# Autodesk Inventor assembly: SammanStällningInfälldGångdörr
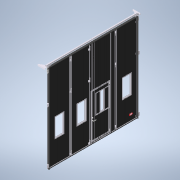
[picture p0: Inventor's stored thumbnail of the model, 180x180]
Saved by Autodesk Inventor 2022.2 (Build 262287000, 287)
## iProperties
Created: 2022-02
Part Number: SammanStällningInfälldGångdörr
Document SubType Name: Assembly
Designer: cl
Author: cl
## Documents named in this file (20)
- G:\AutoCad\Carl Lund\3D-modeller systemlösningar\3D-modell-systemlösning-2022\SammanStällningInfälldGångdörr.iam
- G:\AutoCad\Carl Lund\3D-modeller systemlösningar\3D-modell-systemlösning-2022\Parts\BladKomplett2022.iam
- G:\AutoCad\Carl Lund\3D-modeller systemlösningar\3D-modell-systemlösning-2022\Parts\MellanGångjärnH.ipt
- G:\AutoCad\Carl Lund\3D-modeller systemlösningar\3D-modell-systemlösning-2022\Parts\MellanGångjärnV.ipt
- G:\AutoCad\Carl Lund\3D-modeller systemlösningar\3D-modell-systemlösning-2022\Parts\Karmstyrning.ipt
- G:\AutoCad\Carl Lund\3D-modeller systemlösningar\3D-modell-systemlösning-2022\Parts\KarmgångjärnH.ipt
- G:\AutoCad\Carl Lund\3D-modeller systemlösningar\3D-modell-systemlösning-2022\Parts\KarmgångjärnV.ipt
- G:\AutoCad\Carl Lund\3D-modeller systemlösningar\3D-modell-systemlösning-2022\Parts\SidotätningUppe.ipt
- G:\AutoCad\Carl Lund\3D-modeller systemlösningar\3D-modell-systemlösning-2022\Parts\SidoTätning.ipt
- G:\AutoCad\Carl Lund\3D-modeller systemlösningar\3D-modell-systemlösning-2022\Parts\SläpList.ipt
- G:\AutoCad\Carl Lund\3D-modeller systemlösningar\3D-modell-systemlösning-2022\Parts\GummilistMellan.ipt
- G:\AutoCad\Carl Lund\3D-modeller systemlösningar\3D-modell-systemlösning-2022\Styrande.iam
- G:\AutoCad\Carl Lund\3D-modeller systemlösningar\3D-modell-systemlösning-2022\Parts\GarageregelHöger.ipt
- G:\AutoCad\Carl Lund\3D-modeller systemlösningar\3D-modell-systemlösning-2022\Parts\GarageregelVänster.ipt
- G:\AutoCad\Carl Lund\3D-modeller systemlösningar\3D-modell-systemlösning-2022\Parts\UppställningsbeslagHöger.ipt
- G:\AutoCad\Carl Lund\3D-modeller systemlösningar\3D-modell-systemlösning-2022\Parts\UppställningsbeslagVänster.ipt
- G:\AutoCad\Carl Lund\3D-modeller systemlösningar\3D-modell-systemlösning-2022\Parts\styrrulle.ipt
- G:\AutoCad\Carl Lund\3D-modeller systemlösningar\3D-modell-systemlösning-2022\Parts\Styrskena.ipt
- G:\AutoCad\Carl Lund\3D-modeller systemlösningar\3D-modell-systemlösning-2022\Parts\BladKomplettInfälld2022.iam
- G:\AutoCad\Carl Lund\3D-modeller systemlösningar\3D-modell-systemlösning-2022\Parts\Logga.ipt
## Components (50 placed, 18 different names)
1. BladKomplett2022:1 [sub-assembly] — Mate:1, Mate:2, Flush:1, Flush:2, Flush:3, Flush:8, Flush:28, Flush:29, Mate:28, Flush:30, Mate:42, Flush:73, Mate:39, Mate:43, Mate:47, Mate:48, Flush:99, Flush:100, Flush:101, Flush:102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
2. BladKomplett2022:2 [sub-assembly] — Flush:2, Flush:3, Flush:8, Flush:106, Mate:52, Flush:107, Flush:118, Flush:121, Mate:65, Flush:148, Flush:149, Mate:82, Flush:170, Flush:171, Flush:177
3. BladKomplett2022:3 [sub-assembly] — Flush:30, Flush:101, Flush:102, Mate:53, Flush:114, Flush:115
4. BladKomplett2022:4 [sub-assembly] — Flush:32, Flush:100, Flush:103, Mate:54, Flush:122, Flush:123, Flush:128, Mate:64, Flush:146, Flush:147
5. BladKomplett2022:5 [sub-assembly] — Flush:31, Flush:99, Flush:104, Flush:129, Mate:55, Flush:130, Mate:63, Flush:144, Flush:145, Mate:81, Flush:168, Flush:169
6. Logga:1 — Mate:181, Mate:182, Mate:183
7. BladKomplett2022:6 [sub-assembly] — Mate:28, Flush:28, Flush:29, Flush:31, Flush:32, Mate:38, Flush:74, Mate:49, Mate:50, Flush:131, Flush:134, Flush:137, Mate:56, Flush:138, Flush:139, Mate:58, Mate:59, Mate:62, Flush:142, Flush:143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
8. BladKomplettInfälld2022:1 [sub-assembly] — Flush:176, Flush:177, Flush:178, Mate:177, Flush:179, Flush:180, Flush:181, Mate:178, Flush:187, Flush:188, Flush:189, Mate:180, Flush:190
9. GarageregelHöger:1 — Flush:156, Flush:157, Flush:158
10. GarageregelHöger:2 — Mate:77, Flush:154, Flush:155, Flush:156, Flush:157, Flush:158
11. GarageregelVänster:1 — Flush:161, Flush:162, Flush:163
12. GarageregelVänster:2 — Mate:78, Flush:159, Flush:160, Flush:161, Flush:162, Flush:163
13. Karmstyrning:2 — Mate:38, Mate:56, Flush:138, Flush:141
14. Karmstyrning:3 — Mate:39, Mate:43, Flush:140
15. Karmstyrning:4 — Mate:42, Mate:60, Mate:61, Flush:141
16. KarmgångjärnH:1 — Flush:74, Mate:49, Mate:50, Flush:166, Flush:167, Mate:80
17. KarmgångjärnV:1 — Flush:73, Mate:47, Mate:48, Flush:164, Flush:165, Mate:79
18. Karmstyrning:1 — Flush:139, Mate:58, Mate:59, Flush:140
19. MellanGångjärnV:3 — Flush:110, Flush:111, Flush:113
20. MellanGångjärnV:2 — Flush:108, Flush:109, Flush:110, Flush:111, Flush:112
21. MellanGångjärnV:1 — Flush:106, Mate:52, Flush:107, Flush:108, Flush:109
22. MellanGångjärnH:2 — Flush:116, Flush:117, Flush:118, Flush:119, Flush:120
23. MellanGångjärnH:3 — Flush:119, Flush:120, Flush:121
24. MellanGångjärnH:1 — Mate:53, Flush:114, Flush:115, Flush:116, Flush:117
25. MellanGångjärnV:6 — Flush:124, Flush:125, Flush:126, Flush:127, Flush:128
26. MellanGångjärnV:5 — Flush:126, Flush:127, Flush:129
27. MellanGångjärnV:4 — Mate:54, Flush:122, Flush:123, Flush:124, Flush:125
28. MellanGångjärnH:5 — Flush:132, Flush:133, Flush:134
29. MellanGångjärnH:6 — Flush:135, Flush:136, Flush:137
30. MellanGångjärnH:4 — Mate:55, Flush:130, Flush:131, Flush:132, Flush:133, Flush:135, Flush:136
31. MellanGångjärnV:7 — Flush:181, Mate:178, Flush:182, Flush:183, Flush:184, Flush:185, Flush:186
32. MellanGångjärnV:8 — Flush:183, Flush:184, Flush:187
33. MellanGångjärnV:9 — Flush:185, Flush:186, Flush:188
34. GummilistMellan:6 — Mate:177, Flush:179, Flush:180
35. GummilistMellan:2 — Mate:63, Flush:144, Flush:145
36. GummilistMellan:3 — Mate:64, Flush:146, Flush:147
37. GummilistMellan:4 — Mate:65, Flush:148, Flush:149
38. GummilistMellan:5 — Mate:66, Flush:150, Flush:151
39. SidotätningUppe:1 — Mate:67, Mate:68, Flush:152, Mate:71, Mate:74
40. SidoTätning:1 — Mate:69, Mate:70, Mate:71, Mate:76
41. SidoTätning:2 — Mate:72, Mate:73, Mate:74
42. SläpList:1 — Mate:75, Flush:153, Mate:76
43. GummilistMellan:1 — Mate:62, Flush:142, Flush:143
44. styrrulle:3 — Flush:189, Mate:180, Flush:190
45. UppställningsbeslagVänster:1 — Flush:166, Flush:167, Mate:80
46. styrrulle:1 — Mate:81, Flush:168, Flush:169
47. styrrulle:2 — Mate:82, Flush:170, Flush:171
48. Styrskena:1 — Mate:83, Flush:172, Flush:174, Mate:176, Flush:175, Mate:179
49. Styrskena:2 — Flush:174, Mate:176, Flush:175
50. UppställningsbeslagHöger:1 — Flush:164, Flush:165, Mate:79, Mate:83, Flush:172, Mate:179
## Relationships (151: Flush 101, Mate 50)
- Mate:1: BladKomplett2022:1
- Mate:2: BladKomplett2022:1
- Flush:1: BladKomplett2022:1
- Flush:2: BladKomplett2022:1 ↔ BladKomplett2022:2
- Flush:3: BladKomplett2022:1 ↔ BladKomplett2022:2
- Flush:8: BladKomplett2022:1 ↔ BladKomplett2022:2
- Mate:28: BladKomplett2022:1 ↔ BladKomplett2022:6
- Flush:28: BladKomplett2022:1 ↔ BladKomplett2022:6
- Flush:29: BladKomplett2022:1 ↔ BladKomplett2022:6
- Flush:30: BladKomplett2022:1 ↔ BladKomplett2022:3
- Flush:31: BladKomplett2022:5 ↔ BladKomplett2022:6
- Flush:32: BladKomplett2022:4 ↔ BladKomplett2022:6
- Mate:38: BladKomplett2022:6 ↔ Karmstyrning:2
- Mate:39: BladKomplett2022:1 ↔ Karmstyrning:3
- Mate:42: BladKomplett2022:1 ↔ Karmstyrning:4
- Mate:43: BladKomplett2022:1 ↔ Karmstyrning:3
- Flush:73: BladKomplett2022:1 ↔ KarmgångjärnV:1
- Mate:47: BladKomplett2022:1 ↔ KarmgångjärnV:1
- Mate:48: BladKomplett2022:1 ↔ KarmgångjärnV:1
- Flush:74: BladKomplett2022:6 ↔ KarmgångjärnH:1
- Mate:49: BladKomplett2022:6 ↔ KarmgångjärnH:1
- Mate:50: BladKomplett2022:6 ↔ KarmgångjärnH:1
- Flush:99: BladKomplett2022:1 ↔ BladKomplett2022:5
- Flush:100: BladKomplett2022:1 ↔ BladKomplett2022:4
- Flush:101: BladKomplett2022:1 ↔ BladKomplett2022:3
- Flush:102: BladKomplett2022:1 ↔ BladKomplett2022:3
- Flush:103: BladKomplett2022:1 ↔ BladKomplett2022:4
- Flush:104: BladKomplett2022:1 ↔ BladKomplett2022:5
- Flush:106: BladKomplett2022:2 ↔ MellanGångjärnV:1
- Mate:52: BladKomplett2022:2 ↔ MellanGångjärnV:1
- Flush:107: BladKomplett2022:2 ↔ MellanGångjärnV:1
- Flush:108: MellanGångjärnV:2 ↔ MellanGångjärnV:1
- Flush:109: MellanGångjärnV:2 ↔ MellanGångjärnV:1
- Flush:110: MellanGångjärnV:3 ↔ MellanGångjärnV:2
- Flush:111: MellanGångjärnV:3 ↔ MellanGångjärnV:2
- Flush:112: BladKomplett2022:1 ↔ MellanGångjärnV:2
- Flush:113: BladKomplett2022:1 ↔ MellanGångjärnV:3
- Mate:53: BladKomplett2022:3 ↔ MellanGångjärnH:1
- Flush:114: BladKomplett2022:3 ↔ MellanGångjärnH:1
- Flush:115: BladKomplett2022:3 ↔ MellanGångjärnH:1
- Flush:116: MellanGångjärnH:2 ↔ MellanGångjärnH:1
- Flush:117: MellanGångjärnH:2 ↔ MellanGångjärnH:1
- Flush:118: BladKomplett2022:2 ↔ MellanGångjärnH:2
- Flush:119: MellanGångjärnH:2 ↔ MellanGångjärnH:3
- Flush:120: MellanGångjärnH:2 ↔ MellanGångjärnH:3
- Flush:121: BladKomplett2022:2 ↔ MellanGångjärnH:3
- Mate:54: BladKomplett2022:4 ↔ MellanGångjärnV:4
- Flush:122: BladKomplett2022:4 ↔ MellanGångjärnV:4
- Flush:123: BladKomplett2022:4 ↔ MellanGångjärnV:4
- Flush:124: MellanGångjärnV:6 ↔ MellanGångjärnV:4
- Flush:125: MellanGångjärnV:6 ↔ MellanGångjärnV:4
- Flush:126: MellanGångjärnV:6 ↔ MellanGångjärnV:5
- Flush:127: MellanGångjärnV:6 ↔ MellanGångjärnV:5
- Flush:128: BladKomplett2022:4 ↔ MellanGångjärnV:6
- Flush:129: BladKomplett2022:5 ↔ MellanGångjärnV:5
- Mate:55: BladKomplett2022:5 ↔ MellanGångjärnH:4
- Flush:130: BladKomplett2022:5 ↔ MellanGångjärnH:4
- Flush:131: BladKomplett2022:6 ↔ MellanGångjärnH:4
- Flush:132: MellanGångjärnH:5 ↔ MellanGångjärnH:4
- Flush:133: MellanGångjärnH:5 ↔ MellanGångjärnH:4
- Flush:134: BladKomplett2022:6 ↔ MellanGångjärnH:5
- Flush:135: MellanGångjärnH:6 ↔ MellanGångjärnH:4
- Flush:136: MellanGångjärnH:6 ↔ MellanGångjärnH:4
- Flush:137: BladKomplett2022:6 ↔ MellanGångjärnH:6
- Mate:56: BladKomplett2022:6 ↔ Karmstyrning:2
- Flush:138: BladKomplett2022:6 ↔ Karmstyrning:2
- Flush:139: BladKomplett2022:6 ↔ Karmstyrning:1
- Mate:58: BladKomplett2022:6 ↔ Karmstyrning:1
- Mate:59: BladKomplett2022:6 ↔ Karmstyrning:1
- Flush:140: Karmstyrning:3 ↔ Karmstyrning:1
- Mate:60: BladKomplett2022:1 ↔ Karmstyrning:4
- Mate:61: BladKomplett2022:1 ↔ Karmstyrning:4
- Flush:141: Karmstyrning:2 ↔ Karmstyrning:4
- Mate:62: BladKomplett2022:6 ↔ GummilistMellan:1
- Flush:142: BladKomplett2022:6 ↔ GummilistMellan:1
- Flush:143: BladKomplett2022:6 ↔ GummilistMellan:1
- Mate:63: BladKomplett2022:5 ↔ GummilistMellan:2
- Flush:144: BladKomplett2022:5 ↔ GummilistMellan:2
- Flush:145: BladKomplett2022:5 ↔ GummilistMellan:2
- Mate:64: BladKomplett2022:4 ↔ GummilistMellan:3
- Flush:146: BladKomplett2022:4 ↔ GummilistMellan:3
- Flush:147: BladKomplett2022:4 ↔ GummilistMellan:3
- Mate:65: BladKomplett2022:2 ↔ GummilistMellan:4
- Flush:148: BladKomplett2022:2 ↔ GummilistMellan:4
- Flush:149: BladKomplett2022:2 ↔ GummilistMellan:4
- Mate:66: BladKomplett2022:1 ↔ GummilistMellan:5
- Flush:150: BladKomplett2022:1 ↔ GummilistMellan:5
- Flush:151: BladKomplett2022:1 ↔ GummilistMellan:5
- Mate:67: BladKomplett2022:1 ↔ SidotätningUppe:1
- Mate:68: BladKomplett2022:1 ↔ SidotätningUppe:1
- Flush:152: BladKomplett2022:6 ↔ SidotätningUppe:1
- Mate:69: BladKomplett2022:6 ↔ SidoTätning:1
- Mate:70: BladKomplett2022:6 ↔ SidoTätning:1
- Mate:71: SidotätningUppe:1 ↔ SidoTätning:1
- Mate:72: BladKomplett2022:1 ↔ SidoTätning:2
- Mate:73: BladKomplett2022:1 ↔ SidoTätning:2
- Mate:74: SidotätningUppe:1 ↔ SidoTätning:2
- Mate:75: BladKomplett2022:1 ↔ SläpList:1
- Flush:153: BladKomplett2022:1 ↔ SläpList:1
- Mate:76: SidoTätning:1 ↔ SläpList:1
- Mate:77: BladKomplett2022:1 ↔ GarageregelHöger:2
- Flush:154: BladKomplett2022:1 ↔ GarageregelHöger:2
- Flush:155: BladKomplett2022:1 ↔ GarageregelHöger:2
- Flush:156: GarageregelHöger:1 ↔ GarageregelHöger:2
- Flush:157: GarageregelHöger:1 ↔ GarageregelHöger:2
- Flush:158: GarageregelHöger:1 ↔ GarageregelHöger:2
- Mate:78: BladKomplett2022:6 ↔ GarageregelVänster:2
- Flush:159: BladKomplett2022:6 ↔ GarageregelVänster:2
- Flush:160: BladKomplett2022:6 ↔ GarageregelVänster:2
- Flush:161: GarageregelVänster:1 ↔ GarageregelVänster:2
- Flush:162: GarageregelVänster:1 ↔ GarageregelVänster:2
- Flush:163: GarageregelVänster:1 ↔ GarageregelVänster:2
- Flush:164: KarmgångjärnV:1 ↔ UppställningsbeslagHöger:1
- Flush:165: KarmgångjärnV:1 ↔ UppställningsbeslagHöger:1
- Mate:79: KarmgångjärnV:1 ↔ UppställningsbeslagHöger:1
- Flush:166: KarmgångjärnH:1 ↔ UppställningsbeslagVänster:1
- Flush:167: KarmgångjärnH:1 ↔ UppställningsbeslagVänster:1
- Mate:80: KarmgångjärnH:1 ↔ UppställningsbeslagVänster:1
- Mate:81: BladKomplett2022:5 ↔ styrrulle:1
- Flush:168: BladKomplett2022:5 ↔ styrrulle:1
- Flush:169: BladKomplett2022:5 ↔ styrrulle:1
- Mate:82: BladKomplett2022:2 ↔ styrrulle:2
- Flush:170: BladKomplett2022:2 ↔ styrrulle:2
- Flush:171: BladKomplett2022:2 ↔ styrrulle:2
- Mate:83: Styrskena:1 ↔ UppställningsbeslagHöger:1
- Flush:172: Styrskena:1 ↔ UppställningsbeslagHöger:1
- Flush:174: Styrskena:1 ↔ Styrskena:2
- Mate:176: Styrskena:1 ↔ Styrskena:2
- Flush:175: Styrskena:1 ↔ Styrskena:2
- Flush:176: BladKomplett2022:1 ↔ BladKomplettInfälld2022:1
- Flush:177: BladKomplett2022:2 ↔ BladKomplettInfälld2022:1
- Flush:178: BladKomplett2022:1 ↔ BladKomplettInfälld2022:1
- Mate:177: BladKomplettInfälld2022:1 ↔ GummilistMellan:6
- Flush:179: BladKomplettInfälld2022:1 ↔ GummilistMellan:6
- Flush:180: BladKomplettInfälld2022:1 ↔ GummilistMellan:6
- Flush:181: BladKomplettInfälld2022:1 ↔ MellanGångjärnV:7
- Mate:178: BladKomplettInfälld2022:1 ↔ MellanGångjärnV:7
- Flush:182: BladKomplett2022:1 ↔ MellanGångjärnV:7
- Flush:183: MellanGångjärnV:7 ↔ MellanGångjärnV:8
- Flush:184: MellanGångjärnV:7 ↔ MellanGångjärnV:8
- Flush:185: MellanGångjärnV:7 ↔ MellanGångjärnV:9
- Flush:186: MellanGångjärnV:7 ↔ MellanGångjärnV:9
- Flush:187: BladKomplettInfälld2022:1 ↔ MellanGångjärnV:8
- Flush:188: BladKomplettInfälld2022:1 ↔ MellanGångjärnV:9
- Mate:179: Styrskena:1 ↔ UppställningsbeslagHöger:1
- Flush:189: BladKomplettInfälld2022:1 ↔ styrrulle:3
- Mate:180: BladKomplettInfälld2022:1 ↔ styrrulle:3
- Flush:190: BladKomplettInfälld2022:1 ↔ styrrulle:3
- Mate:181: Logga:1 ↔ BladKomplett2022:6
- Mate:182: Logga:1 ↔ BladKomplett2022:6
- Mate:183: Logga:1 ↔ BladKomplett2022:6
## Named parameters: Blad2 = 1012.5 mm, Blad3 = 0, Blad4 = 0, Blad5 = 1012.5 mm, MGJ12Djup = 0, MGJ12Bredd = 0, MGJ56Djup = 0, MGJ56Bredd = 0, MGJ23Djup = 48 mm, MGJ45Djup = 48 mm, GarageRegel5 = 0, GarageRegel6 = 0, BladBredd = 987.5 mm, Fönsterhöjd = 862 mm, Blad2_1 = 1012.5 mm, Blad3_1 = 0, Blad4_1 = 0, Blad5_1 = 1012.5 mm, Blad6 = 2025 mm, MGJ12Djup_1 = 0, MGJ12Bredd_1 = 0, MGJ2Djup = 0, MGJ2Bredd = 5012.5 mm, MGJ56Djup_1 = 0, MGJ56Bredd_1 = 0, MGJ23Djup_1 = 48 mm, MGJ45Djup_1 = 48 mm, GarageRegel5_1 = 0, GarageRegel6_1 = 0, Styrrulle2Djup = 0, FönsterhöjdStyrning = 862 mm, FönsterKarm = 54 mm, AndraGlasraden = 0, BrösthöjdStyrning2 = 0.0001 mm, InfälldGångDörr = 0, Infälldstyr = 845.83333 mm
